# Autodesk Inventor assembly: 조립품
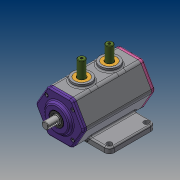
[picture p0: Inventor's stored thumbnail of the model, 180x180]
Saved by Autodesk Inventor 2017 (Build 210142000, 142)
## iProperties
Part Number: 조립품
Material: 일반
Document SubType Name: Assembly
Designer: user
Author: user
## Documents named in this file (11)
- C:\Users\user\Desktop\710606V1044\조립품.iam
- C:\Users\user\Desktop\710606V1044\본체.ipt
- C:\Users\user\Desktop\710606V1044\편심축.ipt
- C:\Users\user\Desktop\710606V1044\앞커버.ipt
- C:\Users\user\Desktop\710606V1044\뒷커버.ipt
- C:\Users\user\Desktop\710606V1044\베어링 6203.ipt
- C:\Users\user\Desktop\710606V1044\베어링 6302.ipt
- C:\Users\user\Desktop\710606V1044\오일실.ipt
- C:\Users\user\Desktop\710606V1044\부시.ipt
- C:\Users\user\Desktop\710606V1044\슬라이더.ipt
- C:\Users\user\Desktop\710606V1044\볼트 M4.ipt
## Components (10 placed, 3 different names)
1. 7-베어링 6203:1 — 각도:2
2. 8-오일실:1
3. 9-M4-소켓머리:1
4. 9-M4-소켓머리:3
5. 9-M4-소켓머리:4
6. 9-M4-소켓머리:5
7. 9-M4-소켓머리:2
8. 9-M4-소켓머리:6
9. 9-M4-소켓머리:7
10. 9-M4-소켓머리:8
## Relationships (1: Angle 1)
- 각도:2 [Angle]: 7-베어링 6203:1
